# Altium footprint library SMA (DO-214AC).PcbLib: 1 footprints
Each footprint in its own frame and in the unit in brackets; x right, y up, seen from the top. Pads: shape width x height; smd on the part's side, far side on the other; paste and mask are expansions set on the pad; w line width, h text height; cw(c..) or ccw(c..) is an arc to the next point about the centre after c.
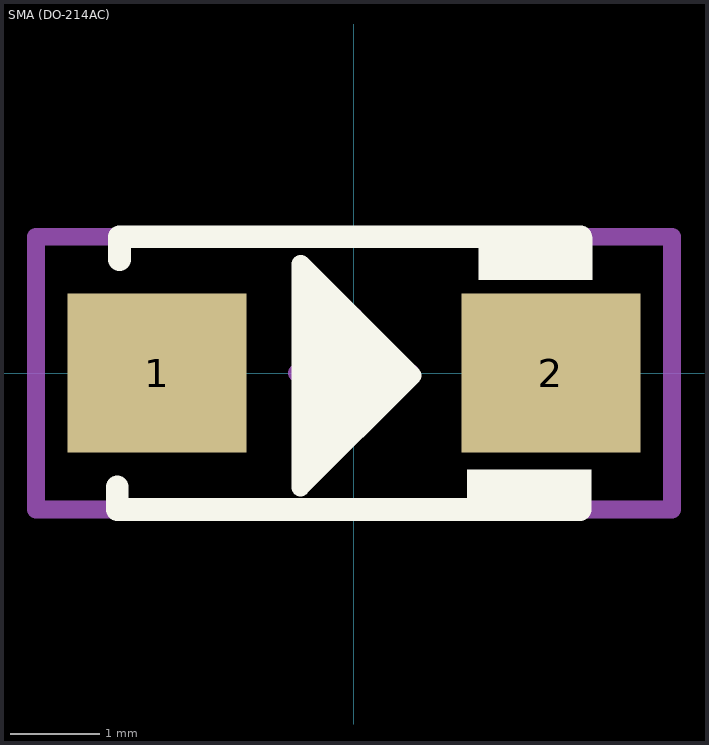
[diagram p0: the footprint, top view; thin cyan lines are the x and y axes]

## SMA (DO-214AC) [mm] "2.79mm x4.5mm"
height 2.29
pads (2):
  rect 2x1.778 smd: 1(-2.2,0) 2(2.2,0)
Top Overlay:
  rectangle: 1.264,-1.543 2.654,-1.079
  rectangle: 1.393,1.041 2.665,1.524
  region: -0.598,1.22 -0.598,-1.279 0.655,-0.025 0.655,-0.024
  lines w0.2: -0.598,-1.279 0.655,-0.025 -0.591,1.22 -0.598,1.22 -0.598,-1.279
  lines w0.254: -2.644,-1.27 -2.644,-1.524 2.526,-1.524 ; -2.62,1.27 -2.62,1.524 2.536,1.524
Mechanical 15:
  lines w0.2: -0.635,0 0.635,0 ; 0,-0.635 0,0.635 ; -3.554,-1.524 3.557,-1.524 3.557,1.524 -3.554,1.524 -3.554,-1.524
3D body "DO-214AC-DIOM5127X23N.stp": height 2.3, standoff 0, extent -2.643,-1.397 2.657,1.403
